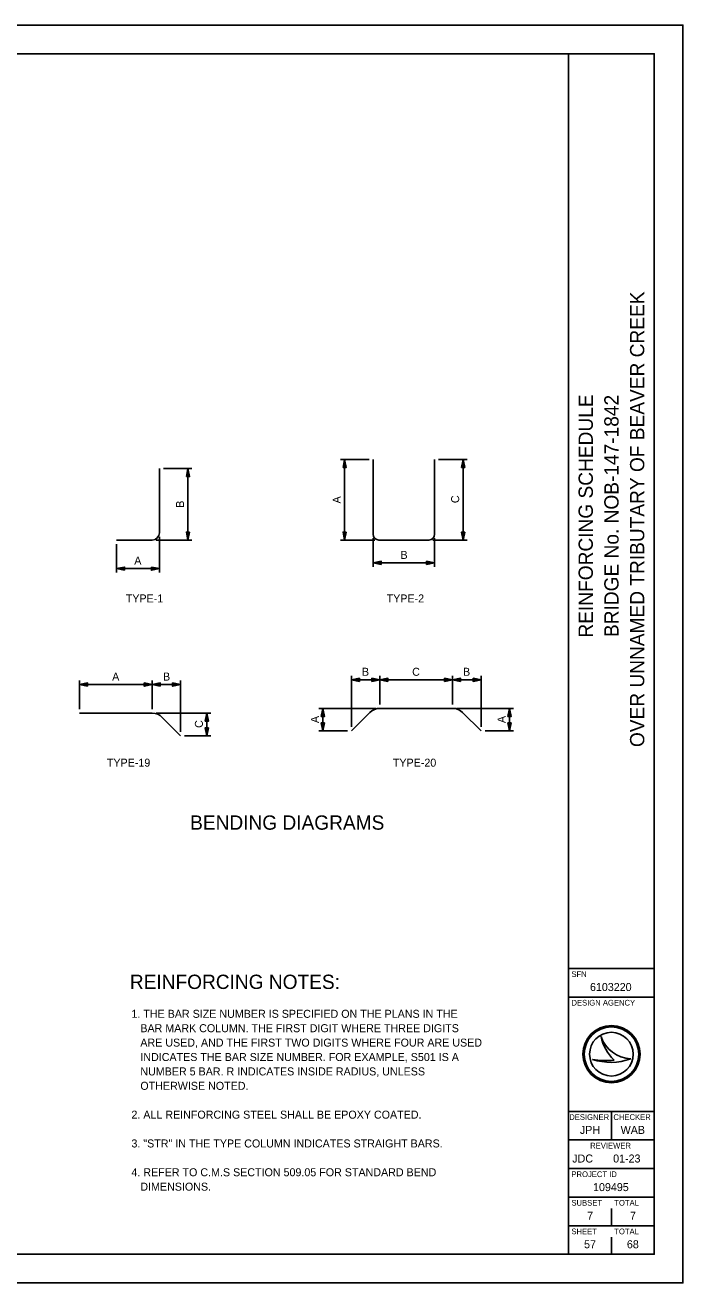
# Model space of a CAD drawing. Extents: x -478 to 216, y -85 to 84.
# Drawn here: x 181.5 to 216.1, y 2 to 68 of the extents above; entities that cross this region are included whole.
import ezdxf

# ---------------------------------------------------------------- set-up
doc = ezdxf.new("R2010")
doc.units = 0
for name, color, linetype in [('BR_P_Gen_NonPerf_Pipe', 7, 'Continuous'), ('BR_P_Gen_Text', 7, 'Continuous'), ('SH_Border', 7, 'Continuous'), ('SH_Cut_Line', 7, 'Continuous'), ('SH_Data', 7, 'Continuous'), ('TX_P_10', 7, 'Continuous')]:
    doc.layers.add(name, color=color, linetype=linetype)

msp = doc.modelspace()

# ---------------------------------------------------------------- linework, layer by layer
at = {"layer": 'BR_P_Gen_Text'}
for p, q in [((199.605, 45.169), (198.105, 45.169)), ((198.315, 45.169), (198.315, 40.937)), ((199.815, 45.169), (199.815, 41.237)), ((203.04, 41.237), (203.04, 45.169)), ((203.249, 45.169), (204.749, 45.169)), ((204.539, 45.169), (204.539, 40.937)), ((188.59, 41.312), (188.59, 44.687)), ((188.8, 44.687), (190.3, 44.687)), ((190.09, 44.687), (190.09, 40.937)), ((186.341, 40.937), (188.215, 40.937)), ((188.425, 40.937), (190.3, 40.937)), ((188.59, 41.102), (188.59, 39.227)), ((199.905, 40.937), (198.105, 40.937)), ((199.815, 41.027), (199.815, 39.527)), ((200.115, 40.937), (202.74, 40.937)), ((202.95, 40.937), (204.749, 40.937)), ((203.04, 41.027), (203.04, 39.527)), ((186.341, 40.727), (186.341, 39.227)), ((199.815, 39.737), (203.04, 39.737)), ((186.341, 39.437), (188.59, 39.437)), ((198.675, 31.13), (198.675, 33.813)), ((200.168, 32.313), (200.168, 33.813)), ((200.168, 32.313), (200.168, 33.813)), ((203.982, 32.313), (203.982, 33.813)), ((203.982, 32.313), (203.982, 33.813)), ((205.476, 31.13), (205.476, 33.813)), ((184.398, 32.061), (184.398, 33.561)), ((188.212, 33.351), (184.398, 33.351)), ((188.212, 32.061), (188.212, 33.561)), ((188.212, 32.061), (188.212, 33.561)), ((188.212, 33.351), (189.705, 33.351)), ((189.705, 30.878), (189.705, 33.561)), ((198.675, 33.603), (200.168, 33.603)), ((200.168, 33.603), (203.982, 33.603)), ((205.476, 33.603), (203.982, 33.603)), ((188.212, 31.851), (184.398, 31.851)), ((188.422, 31.851), (191.293, 31.851)), ((191.083, 30.668), (191.083, 31.851)), ((199.958, 32.103), (196.965, 32.103)), ((197.175, 32.103), (197.175, 30.92)), ((199.638, 31.883), (198.675, 30.92)), ((203.982, 32.103), (200.168, 32.103)), ((204.192, 32.103), (207.186, 32.103)), ((204.513, 31.883), (205.476, 30.92)), ((206.976, 32.103), (206.976, 30.92)), ((188.743, 31.631), (189.705, 30.668)), ((189.915, 30.668), (191.293, 30.668)), ((198.465, 30.92), (196.965, 30.92)), ((205.686, 30.92), (207.186, 30.92))]:
    msp.add_line(p, q, dxfattribs=at)
for points in [[(198.231, 44.749), (198.315, 45.169), (198.399, 44.749)], [(204.455, 44.749), (204.539, 45.169), (204.623, 44.749)], [(190.006, 44.267), (190.09, 44.687), (190.174, 44.267)], [(190.174, 41.357), (190.09, 40.937), (190.006, 41.357)], [(198.399, 41.357), (198.315, 40.937), (198.231, 41.357)], [(204.623, 41.357), (204.539, 40.937), (204.455, 41.357)], [(200.235, 39.653), (199.815, 39.737), (200.235, 39.821)], [(202.62, 39.821), (203.04, 39.737), (202.62, 39.653)], [(186.76, 39.353), (186.341, 39.437), (186.76, 39.521)], [(188.17, 39.521), (188.59, 39.437), (188.17, 39.353)], [(199.095, 33.519), (198.675, 33.603), (199.095, 33.687)], [(199.748, 33.687), (200.168, 33.603), (199.748, 33.519)], [(200.588, 33.519), (200.168, 33.603), (200.588, 33.687)], [(203.562, 33.687), (203.982, 33.603), (203.562, 33.519)], [(204.402, 33.519), (203.982, 33.603), (204.402, 33.687)], [(205.056, 33.687), (205.476, 33.603), (205.056, 33.519)], [(184.818, 33.267), (184.398, 33.351), (184.818, 33.435)], [(187.792, 33.435), (188.212, 33.351), (187.792, 33.267)], [(188.632, 33.267), (188.212, 33.351), (188.632, 33.435)], [(189.285, 33.435), (189.705, 33.351), (189.285, 33.267)], [(190.999, 31.431), (191.083, 31.851), (191.167, 31.431)], [(197.091, 31.683), (197.175, 32.103), (197.259, 31.683)], [(206.892, 31.683), (206.976, 32.103), (207.06, 31.683)], [(191.167, 31.088), (191.083, 30.668), (190.999, 31.088)], [(197.259, 31.34), (197.175, 30.92), (197.091, 31.34)], [(207.06, 31.34), (206.976, 30.92), (206.892, 31.34)]]:
    msp.add_lwpolyline(points, close=True, dxfattribs=at)
for centre, radius, start, end in [((188.215, 41.312), 0.375, 270, 360), ((200.115, 41.237), 0.3, 180, 270), ((202.74, 41.237), 0.3, 270, 360), ((188.212, 31.101), 0.75, 45, 90), ((200.168, 31.353), 0.75, 90, 135), ((203.982, 31.353), 0.75, 45, 90)]:
    msp.add_arc(centre, radius, start, end, dxfattribs=at)
at = {"layer": 'SH_Border'}
for p, q in [((210.075, 3.456), (210.075, 66.456)), ((210.075, 18.456), (214.575, 18.456)), ((210.075, 16.956), (214.575, 16.956)), ((210.075, 10.956), (214.575, 10.956)), ((212.325, 10.956), (212.325, 9.456)), ((210.075, 9.456), (214.575, 9.456)), ((210.075, 7.956), (214.575, 7.956)), ((210.075, 6.456), (214.575, 6.456)), ((210.075, 4.956), (214.575, 4.956))]:
    msp.add_line(p, q, dxfattribs=at)
msp.add_lwpolyline([(118.576, 66.456), (214.575, 66.456), (214.575, 3.456), (118.576, 3.456)], close=True, dxfattribs=at)
at = {"layer": 'SH_Cut_Line'}
msp.add_lwpolyline([(114.076, 1.956), (216.075, 1.956), (216.075, 67.956), (114.076, 67.956)], close=True, dxfattribs=at)
at = {"layer": 'SH_Data'}
for p, q in [((211.778, 14.885), (211.778, 14.885)), ((212.325, 13.956), (212.325, 13.956)), ((211.327, 13.685), (211.327, 13.685)), ((213.337, 13.712), (213.337, 13.712)), ((212.325, 4.956), (212.325, 5.856)), ((211.2, 3.981), (211.2, 3.981)), ((212.325, 3.456), (212.325, 4.356))]:
    msp.add_line(p, q, dxfattribs=at)
for radius in [1.5, 1.43, 1.43, 1.147]:
    msp.add_circle((212.325, 13.956), radius, dxfattribs=at)
for centre, radius, start, end in [((213.423, 15.449), 1.74, 198.92567, 198.93195), ((214.115, 15.366), 2.387, 191.63793, 191.64215), ((213.423, 15.449), 1.74, 198.93195, 267.16574), ((214.115, 15.366), 2.387, 191.64215, 226.09467), ((212.294, 16.566), 3.039, 251.45764, 290.08324), ((212.019, 17.419), 3.798, 259.49639, 259.49952), ((212.294, 16.566), 3.039, 251.45274, 251.45764), ((212.019, 17.419), 3.798, 259.49952, 276.66723)]:
    msp.add_arc(centre, radius, start, end, dxfattribs=at)

# ---------------------------------------------------------------- texts
at = {"layer": 'BR_P_Gen_NonPerf_Pipe'}
for s, p in [('1. THE BAR SIZE NUMBER IS SPECIFIED ON THE PLANS IN THE', (187.12, 15.865)), ('   BAR MARK COLUMN. THE FIRST DIGIT WHERE THREE DIGITS', (187.12, 15.109)), ('   ARE USED, AND THE FIRST TWO DIGITS WHERE FOUR ARE USED ', (187.12, 14.353)), ('   INDICATES THE BAR SIZE NUMBER. FOR EXAMPLE, S501 IS A ', (187.12, 13.597)), ('   NUMBER 5 BAR. R INDICATES INSIDE RADIUS, UNLESS', (187.12, 12.841)), ('   OTHERWISE NOTED.', (187.12, 12.085)), ('2. ALL REINFORCING STEEL SHALL BE EPOXY COATED.', (187.12, 10.573)), ('3. "STR" IN THE TYPE COLUMN INDICATES STRAIGHT BARS.', (187.12, 9.061)), ('4. REFER TO C.M.S SECTION 509.05 FOR STANDARD BEND ', (187.12, 7.549)), ('   DIMENSIONS.', (187.12, 6.793))]:
    msp.add_text(s, height=0.42, dxfattribs=at).set_placement(p)
at = {"layer": 'BR_P_Gen_Text'}
for s, p in [('B', (189.88, 42.632)), ('A', (198.105, 42.857)), ('C', (204.329, 42.873)), ('A', (196.965, 31.331)), ('A', (206.766, 31.331)), ('C', (190.873, 31.079))]:
    msp.add_text(s, height=0.42, rotation=90, dxfattribs=at).set_placement(p)
for s, p in [('B', (201.247, 39.947)), ('A', (187.269, 39.647)), ('A', (186.109, 33.561)), ('B', (188.779, 33.561)), ('B', (199.225, 33.813)), ('C', (201.861, 33.813)), ('B', (204.533, 33.813))]:
    msp.add_text(s, height=0.42, dxfattribs=at).set_placement(p)
at = {"layer": 'SH_Data'}
for s, p in [('OVER UNNAMED TRIBUTARY OF BEAVER CREEK', (214.05, 30.072)), ('REINFORCING SCHEDULE', (211.35, 35.817)), ('BRIDGE No. NOB-147-1842', (212.7, 35.846))]:
    msp.add_text(s, height=0.75, rotation=90, dxfattribs=at).set_placement(p)
for s, height, p in [('BENDING DIAGRAMS', 0.75, (190.203, 25.736)), ('REINFORCING NOTES:', 0.75, (187.038, 17.378)), ('SFN', 0.3, (210.225, 18.006)), ('6103220', 0.42, (211.198, 17.271)), ('DESIGN AGENCY', 0.3, (210.225, 16.506)), ('DESIGNER', 0.3, (210.108, 10.506)), ('CHECKER', 0.3, (212.428, 10.506)), ('JPH', 0.42, (210.67, 9.771)), ('WAB', 0.42, (212.809, 9.771)), ('REVIEWER', 0.3, (211.21, 9.006)), ('JDC', 0.42, (210.267, 8.271)), ('01-23', 0.42, (212.414, 8.271)), ('PROJECT ID', 0.3, (210.225, 7.506)), ('109495', 0.42, (211.359, 6.771)), ('SUBSET', 0.3, (210.225, 6.006)), ('TOTAL', 0.3, (212.475, 6.006)), ('7', 0.42, (211.051, 5.271)), ('7', 0.42, (213.301, 5.271)), ('SHEET', 0.3, (210.225, 4.506)), ('TOTAL', 0.3, (212.475, 4.506)), ('57', 0.42, (210.888, 3.771)), ('68', 0.42, (213.137, 3.771))]:
    msp.add_text(s, height=height, dxfattribs=at).set_placement(p)
at = {"layer": 'TX_P_10'}
for s, p in [('TYPE-1', (186.824, 37.662)), ('TYPE-2', (200.521, 37.662)), ('TYPE-19', (185.832, 29.043)), ('TYPE-20', (200.849, 29.043))]:
    msp.add_text(s, height=0.42, dxfattribs=at).set_placement(p)

doc.saveas('drawing.dxf')
